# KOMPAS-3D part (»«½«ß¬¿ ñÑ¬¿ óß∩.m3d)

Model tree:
1. Эскиз:1
2. Операция выдавливания:1
     Толщина стенки 1 = 2.3; Толщина стенки 2 = 2.3; Расстояние 1 = 0.6; Расстояние 2 = 0.6
3. Эскиз:2
4. Операция выдавливания:2
     Толщина стенки 1 = 2.3; Толщина стенки 2 = 2.3; Расстояние 1 = 0.6; Расстояние 2 = 0.6
5. Эскиз:3
6. Вырезать элемент выдавливания:1
     Толщина стенки 1 = 3; Толщина стенки 2 = 3; Расстояние 1 = 10
